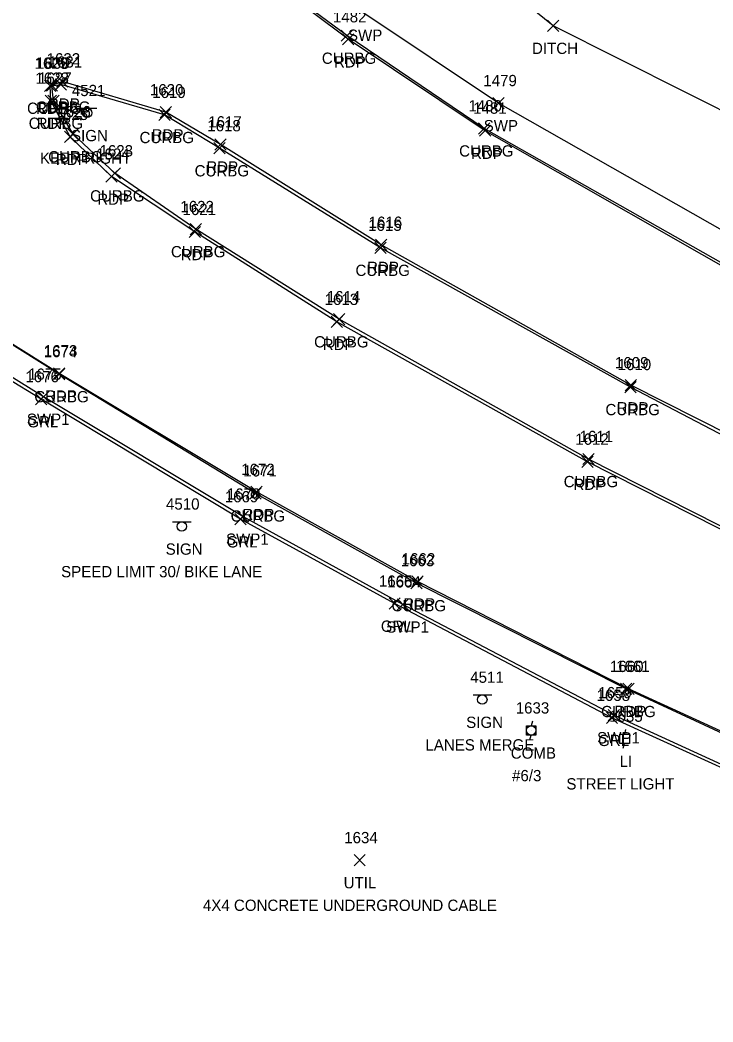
# Model space of a CAD drawing. Extents: x 1690689 to 1696275, y 438760 to 444007.
# Drawn here: x 1691973.1 to 1692096, y 439004.8 to 439182.5 of the extents above; entities that cross this region are included whole.
import ezdxf

# ---------------------------------------------------------------- set-up
doc = ezdxf.new("R2010")
doc.units = 0
for name, color, linetype in [('D_A', 7, 'Continuous'), ('D_TIC', 7, 'Continuous'), ('DD', 7, 'Continuous'), ('P_A', 7, 'Continuous'), ('P_I', 7, 'Continuous'), ('P_TIC', 7, 'Continuous'), ('PET', 7, 'Continuous'), ('R_A', 7, 'Continuous'), ('R_I', 7, 'Continuous'), ('R_TIC', 7, 'Continuous'), ('RC', 7, 'Continuous'), ('RGR', 7, 'Continuous'), ('RSW', 7, 'Continuous'), ('S_A', 7, 'Continuous'), ('S_C', 7, 'Continuous'), ('S_I', 7, 'Continuous'), ('SSGN', 7, 'Continuous'), ('U_A', 7, 'Continuous'), ('U_C', 7, 'Continuous'), ('U_I', 7, 'Continuous'), ('UDEFAULT', 7, 'Continuous'), ('ULP', 7, 'Continuous'), ('UP', 7, 'Continuous')]:
    doc.layers.add(name, color=color, linetype=linetype)

msp = doc.modelspace()

# ---------------------------------------------------------------- linework, layer by layer
at = {"layer": 'D_TIC'}
for points in [[(1692066.68, 439180.46), (1692068.68, 439182.46)], [(1692068.68, 439180.46), (1692066.68, 439182.46)]]:
    msp.add_lwpolyline(points, dxfattribs=at)
at = {"layer": 'DD'}
msp.add_lwpolyline([(1692601.69, 439017.79), (1692563.37, 439021.21), (1692508.43, 439031.44), (1692465.47, 439040.14), (1692415.19, 439051.66), (1692376.4, 439060.91), (1692339.07, 439071.12), (1692282.68, 439087.44), (1692232.86, 439105.49), (1692192.88, 439120.62), (1692157.57, 439136.03), (1692114.74, 439157.79), (1692067.68, 439181.46), (1692012.38, 439226.11), (1692016.4, 439238.61), (1692018.77, 439248.28), (1692013.27, 439253.9), (1692009.52, 439256.4)], dxfattribs=at)
at = {"layer": 'P_TIC'}
for points in [[(1692030.29, 439178.06), (1692032.29, 439180.06)], [(1692032.29, 439178.06), (1692030.29, 439180.06)], [(1691977.42, 439169.83), (1691979.42, 439171.83)], [(1691979.42, 439169.83), (1691977.42, 439171.83)], [(1691979.54, 439170.6), (1691981.54, 439172.6)], [(1691981.54, 439170.6), (1691979.54, 439172.6)], [(1691979.54, 439170.6), (1691981.54, 439172.6)], [(1691981.54, 439170.6), (1691979.54, 439172.6)], [(1691977.54, 439167.17), (1691979.54, 439169.17)], [(1691979.54, 439167.17), (1691977.54, 439169.17)], [(1691997.95, 439165.12), (1691999.95, 439167.12)], [(1691999.95, 439165.12), (1691997.95, 439167.12)], [(1691980.95, 439160.75), (1691982.95, 439162.75)], [(1691982.95, 439160.75), (1691980.95, 439162.75)], [(1692054.61, 439161.86), (1692056.61, 439163.86)], [(1692056.61, 439161.86), (1692054.61, 439163.86)], [(1692007.65, 439159.43), (1692009.65, 439161.43)], [(1692009.65, 439159.43), (1692007.65, 439161.43)], [(1691988.31, 439153.72), (1691990.31, 439155.72)], [(1691990.31, 439153.72), (1691988.31, 439155.72)], [(1692003.08, 439143.9), (1692005.08, 439145.9)], [(1692005.08, 439143.9), (1692003.08, 439145.9)], [(1692036.17, 439141.63), (1692038.17, 439143.63)], [(1692038.17, 439141.63), (1692036.17, 439143.63)], [(1692028.3, 439127.96), (1692030.3, 439129.96)], [(1692030.3, 439127.96), (1692028.3, 439129.96)], [(1691979.04, 439118.84), (1691981.04, 439120.84)], [(1691981.04, 439118.84), (1691979.04, 439120.84)], [(1692080.46, 439116.73), (1692082.46, 439118.73)], [(1692082.46, 439116.73), (1692080.46, 439118.73)], [(1692072.76, 439103.17), (1692074.76, 439105.17)], [(1692074.76, 439103.17), (1692072.76, 439105.17)], [(1692014.06, 439097.81), (1692016.06, 439099.81)], [(1692016.06, 439097.81), (1692014.06, 439099.81)], [(1692042.59, 439081.96), (1692044.59, 439083.96)], [(1692044.59, 439081.96), (1692042.59, 439083.96)], [(1692080.06, 439062.89), (1692082.06, 439064.89)], [(1692082.06, 439062.89), (1692080.06, 439064.89)]]:
    msp.add_lwpolyline(points, dxfattribs=at)
at = {"layer": 'PET'}
for points in [[(1692506.42, 439007.58), (1692409.86, 439027.99), (1692378.72, 439035.13), (1692333.82, 439046.83), (1692278.1, 439062.9), (1692234.78, 439077.7), (1692205.8, 439088.84), (1692153.42, 439111.21), (1692107.02, 439133.53), (1692055.61, 439162.86), (1692031.29, 439179.06), (1692011.62, 439193.84), (1692002.42, 439202.85), (1692001.04, 439204.48), (1691998.47, 439209.28), (1691996.33, 439214.88), (1691994.6, 439223.82), (1691994.86, 439229.58), (1691997.14, 439239.21), (1692003.46, 439250.16), (1692011.11, 439259.34), (1692010.11, 439260.69)], [(1692765.95, 438921.86), (1692671.87, 438941.97), (1692616.75, 438954.47), (1692587.11, 438960.22), (1692543.54, 438967.18), (1692506.54, 438970.09), (1692469.43, 438975.08), (1692419.94, 438983.98), (1692360.97, 438996.85), (1692305.33, 439011.12), (1692283.25, 439017.76), (1692237.36, 439032.88), (1692203.62, 439044.85), (1692162.64, 439062.19), (1692110.81, 439085.42), (1692073.76, 439104.17), (1692029.3, 439128.96), (1692004.08, 439144.9), (1691989.31, 439154.72), (1691981.95, 439161.75), (1691978.54, 439168.17), (1691978.42, 439170.83), (1691980.54, 439171.6)], [(1692767.64, 438925.55), (1692673.48, 438945.69), (1692617.32, 438957.74), (1692543.2, 438973.83), (1692470.55, 438989.57), (1692418.41, 439000.55), (1692365.96, 439012.47), (1692309.7, 439026.97), (1692288.49, 439033.25), (1692244.35, 439047.34), (1692210.04, 439059.59), (1692168.81, 439075.98), (1692116.96, 439099.81), (1692081.46, 439117.73), (1692037.17, 439142.63), (1692008.65, 439160.43), (1691998.95, 439166.12), (1691980.54, 439171.6)], [(1692485.07, 438945.57), (1692435.03, 438955.4), (1692385.23, 438965.25), (1692340.43, 438974.31), (1692296.87, 438984.77), (1692272.43, 438991.45), (1692235.97, 439002.41), (1692197.17, 439015.62), (1692153.62, 439031.87), (1692118.48, 439046.77), (1692081.06, 439063.89), (1692043.59, 439082.96), (1692015.06, 439098.81), (1691980.04, 439119.84), (1691962.57, 439130.66), (1691955.71, 439134.26), (1691947.97, 439136.72), (1691941.75, 439137.91), (1691935.77, 439138.24), (1691931.84, 439138.11), (1691929.14, 439137.6), (1691914.86, 439134.28)]]:
    msp.add_lwpolyline(points, dxfattribs=at)
at = {"layer": 'R_TIC'}
for points in [[(1692030.04, 439178.71), (1692032.04, 439180.71)], [(1692032.04, 439178.71), (1692030.04, 439180.71)], [(1691977.75, 439169.84), (1691979.75, 439171.84)], [(1691979.75, 439169.84), (1691977.75, 439171.84)], [(1691979.34, 439170.05), (1691981.34, 439172.05)], [(1691981.34, 439170.05), (1691979.34, 439172.05)], [(1691979.34, 439170.05), (1691981.34, 439172.05)], [(1691981.34, 439170.05), (1691979.34, 439172.05)], [(1691978.04, 439167.18), (1691980.04, 439169.18)], [(1691980.04, 439167.18), (1691978.04, 439169.18)], [(1692056.98, 439166.75), (1692058.98, 439168.75)], [(1692058.98, 439166.75), (1692056.98, 439168.75)], [(1691997.71, 439164.65), (1691999.71, 439166.65)], [(1691999.71, 439164.65), (1691997.71, 439166.65)], [(1691981.48, 439161.24), (1691983.48, 439163.24)], [(1691983.48, 439161.24), (1691981.48, 439163.24)], [(1692054.41, 439162.27), (1692056.41, 439164.27)], [(1692056.41, 439162.27), (1692054.41, 439164.27)], [(1692007.48, 439158.75), (1692009.48, 439160.75)], [(1692009.48, 439158.75), (1692007.48, 439160.75)], [(1691988.92, 439154.3), (1691990.92, 439156.3)], [(1691990.92, 439154.3), (1691988.92, 439156.3)], [(1692003.27, 439144.41), (1692005.27, 439146.41)], [(1692005.27, 439144.41), (1692003.27, 439146.41)], [(1692036.02, 439141.1), (1692038.02, 439143.1)], [(1692038.02, 439141.1), (1692036.02, 439143.1)], [(1692028.68, 439128.43), (1692030.68, 439130.43)], [(1692030.68, 439128.43), (1692028.68, 439130.43)], [(1691979.03, 439118.7), (1691981.03, 439120.7)], [(1691981.03, 439118.7), (1691979.03, 439120.7)], [(1692080.37, 439116.41), (1692082.37, 439118.41)], [(1692082.37, 439116.41), (1692080.37, 439118.41)], [(1691976.25, 439114.7), (1691978.25, 439116.7)], [(1691978.25, 439114.7), (1691976.25, 439116.7)], [(1691975.83, 439114.26), (1691977.83, 439116.26)], [(1691977.83, 439114.26), (1691975.83, 439116.26)], [(1692072.96, 439103.65), (1692074.96, 439105.65)], [(1692074.96, 439103.65), (1692072.96, 439105.65)], [(1692013.87, 439097.55), (1692015.87, 439099.55)], [(1692015.87, 439097.55), (1692013.87, 439099.55)], [(1692011.59, 439093.44), (1692013.59, 439095.44)], [(1692013.59, 439093.44), (1692011.59, 439095.44)], [(1692011.2, 439092.97), (1692013.2, 439094.97)], [(1692013.2, 439092.97), (1692011.2, 439094.97)], [(1692042.41, 439081.64), (1692044.41, 439083.64)], [(1692044.41, 439081.64), (1692042.41, 439083.64)], [(1692038.55, 439078.01), (1692040.55, 439080.01)], [(1692040.55, 439078.01), (1692038.55, 439080.01)], [(1692040.02, 439077.87), (1692042.02, 439079.87)], [(1692042.02, 439077.87), (1692040.02, 439079.87)], [(1692079.62, 439062.88), (1692081.62, 439064.88)], [(1692081.62, 439062.88), (1692079.62, 439064.88)], [(1692077.11, 439057.76), (1692079.11, 439059.76)], [(1692079.11, 439057.76), (1692077.11, 439059.76)], [(1692077.43, 439058.23), (1692079.43, 439060.23)], [(1692079.43, 439058.23), (1692077.43, 439060.23)]]:
    msp.add_lwpolyline(points, dxfattribs=at)
at = {"layer": 'RC'}
for points in [[(1692458.66, 439018.07), (1692409.83, 439028.32), (1692378.84, 439035.52), (1692333.85, 439047.39), (1692278.2, 439063.36), (1692234.93, 439078.32), (1692206.05, 439089.01), (1692153.68, 439111.65), (1692107.21, 439133.95), (1692055.41, 439163.27), (1692031.04, 439179.71), (1692011.71, 439194.03), (1692002.37, 439202.91), (1692001.39, 439204.32), (1691998.83, 439209.21), (1691996.61, 439215.03), (1691994.98, 439223.75), (1691995.26, 439229.27), (1691997.49, 439239.08), (1692003.79, 439249.87), (1692007.64, 439254.1)], [(1692766.36, 438922.45), (1692671.96, 438942.46), (1692616.73, 438954.89), (1692587.1, 438960.64), (1692543.8, 438967.52), (1692506.49, 438970.64), (1692469.42, 438975.23), (1692419.64, 438984.49), (1692361.22, 438997.2), (1692305.35, 439011.89), (1692283.35, 439018.43), (1692237.58, 439033.34), (1692203.77, 439045.28), (1692162.83, 439062.74), (1692110.99, 439085.87), (1692073.96, 439104.65), (1692029.68, 439129.43), (1692004.27, 439145.41), (1691989.92, 439155.3), (1691982.48, 439162.24), (1691979.04, 439168.18), (1691978.75, 439170.84), (1691980.34, 439171.05)], [(1692767.42, 438924.95), (1692673.21, 438945.2), (1692617.12, 438957.34), (1692543.19, 438973.28), (1692470.51, 438988.93), (1692418.35, 439000.23), (1692365.64, 439012.16), (1692309.62, 439026.54), (1692288.66, 439032.69), (1692244.17, 439046.9), (1692209.98, 439058.96), (1692168.78, 439075.61), (1692116.61, 439099.03), (1692081.37, 439117.41), (1692037.02, 439142.1), (1692008.48, 439159.75), (1691998.71, 439165.65), (1691980.34, 439171.05)], [(1692118.26, 439046.46), (1692080.62, 439063.88), (1692043.41, 439082.64), (1692014.87, 439098.55), (1691980.03, 439119.7), (1691962.53, 439130.63), (1691955.49, 439134.15), (1691948, 439136.19), (1691941.67, 439137.59), (1691935.68, 439137.8), (1691931.95, 439137.88), (1691929.4, 439137.32), (1691914.96, 439133.89), (1691889.69, 439124), (1691873.84, 439117.58), (1691827.75, 439101.2)]]:
    msp.add_lwpolyline(points, dxfattribs=at)
at = {"layer": 'RGR'}
msp.add_lwpolyline([(1692115.78, 439041.61), (1692078.11, 439058.76), (1692039.55, 439079.01), (1692012.2, 439093.97), (1691976.83, 439115.26), (1691958.12, 439126.58), (1691952.53, 439129.47), (1691946.71, 439131.26), (1691941.09, 439132.25), (1691934.38, 439132.69), (1691928.78, 439132.18), (1691917.8, 439129.38), (1691893.03, 439121.47), (1691884.65, 439119.11), (1691880.06, 439116.74), (1691874.97, 439112.92)], dxfattribs=at)
at = {"layer": 'RSW'}
for points in [[(1692665.59, 438979.47), (1692633.47, 438986.11), (1692606.01, 438992.31), (1692555.68, 439002.49), (1692507.66, 439012.62), (1692459.75, 439022.83), (1692410.78, 439033.39), (1692380.42, 439040.26), (1692334.91, 439052.16), (1692279.52, 439068.27), (1692236.35, 439083.17), (1692207.73, 439093.85), (1692155.83, 439116.19), (1692109.79, 439138.3), (1692057.98, 439167.75), (1692033.9, 439183.79), (1692014.53, 439197.98), (1692008.04, 439204.8), (1692006.24, 439207.82), (1692001.39, 439204.32)], [(1692637.9, 438909.12), (1692604.66, 438916.25), (1692559.9, 438925.87), (1692526.71, 438932.34), (1692484.3, 438940.72), (1692434.26, 438950.4), (1692384.3, 438960.21), (1692339.45, 438969.35), (1692295.64, 438980.27), (1692271.48, 438986.87), (1692234.38, 438997.66), (1692195.38, 439010.77), (1692151.68, 439027.12), (1692116.08, 439041.96), (1692078.43, 439059.23), (1692041.02, 439078.87), (1692012.59, 439094.44), (1691977.25, 439115.7), (1691958.72, 439127.11), (1691952.86, 439130.25), (1691946.68, 439131.94), (1691948, 439136.19)]]:
    msp.add_lwpolyline(points, dxfattribs=at)
at = {"layer": 'SSGN'}
for p, q in [((1691983.35, 439166.84), (1691986.68, 439166.84)), ((1691984.99, 439166.01), (1691984.99, 439166.01)), ((1692000.13, 439093.54), (1692003.47, 439093.54)), ((1692001.78, 439092.7), (1692001.78, 439092.7)), ((1692053.46, 439062.83), (1692056.79, 439062.83)), ((1692055.1, 439061.99), (1692055.1, 439061.99))]:
    msp.add_line(p, q, dxfattribs=at)
for centre in [(1691984.99, 439166.01), (1692001.78, 439092.7), (1692055.1, 439061.99)]:
    msp.add_circle(centre, 0.833, dxfattribs=at)
at = {"layer": 'UDEFAULT'}
for points in [[(1692032.34, 439032.53), (1692034.34, 439034.53)], [(1692034.34, 439032.53), (1692032.34, 439034.53)]]:
    msp.add_lwpolyline(points, dxfattribs=at)
at = {"layer": 'ULP'}
for p, q in [((1692080.52, 439056.72), (1692080.35, 439055.89)), ((1692079.52, 439054.22), (1692079.52, 439055.89)), ((1692079.52, 439055.89), (1692081.19, 439055.89)), ((1692080.35, 439055.06), (1692080.35, 439055.06)), ((1692081.19, 439055.89), (1692081.19, 439054.22)), ((1692081.19, 439054.22), (1692079.52, 439054.22)), ((1692080.1, 439053.39), (1692080.35, 439054.22))]:
    msp.add_line(p, q, dxfattribs=at)
at = {"layer": 'UP'}
for p, q in [((1692064.02, 439058.19), (1692063.77, 439057.36)), ((1692062.93, 439055.69), (1692062.93, 439057.36)), ((1692062.93, 439057.36), (1692064.6, 439057.36)), ((1692063.77, 439056.52), (1692063.77, 439056.52)), ((1692064.6, 439057.36), (1692064.6, 439055.69)), ((1692064.6, 439055.69), (1692062.93, 439055.69)), ((1692063.52, 439054.86), (1692063.77, 439055.69))]:
    msp.add_line(p, q, dxfattribs=at)
msp.add_circle((1692063.77, 439056.52), 0.833, dxfattribs=at)

# ---------------------------------------------------------------- texts
at = {"layer": 'D_A'}
msp.add_text('DITCH', height=2, dxfattribs=at).set_placement((1692063.92, 439176.46))
at = {"layer": 'P_A'}
for p in [(1692028.78, 439174.06), (1691978.03, 439166.6), (1691978.03, 439166.6), (1691975.91, 439165.83), (1691976.03, 439163.17), (1691996.44, 439161.12), (1692053.1, 439157.86), (1691979.44, 439156.75), (1692006.13, 439155.43), (1691986.79, 439149.72), (1692001.57, 439139.9), (1692034.66, 439137.63), (1692026.79, 439123.96), (1691977.52, 439114.84), (1692078.94, 439112.73), (1692071.25, 439099.17), (1692012.55, 439093.81), (1692041.08, 439077.96), (1692078.55, 439058.89)]:
    msp.add_text('RDP', height=2, dxfattribs=at).set_placement(p)
at = {"layer": 'P_I'}
for s, p in [('1482', (1692028.6, 439182.06)), ('1629', (1691975.67, 439173.83)), ('1632', (1691977.8, 439174.6)), ('1632', (1691977.8, 439174.6)), ('1628', (1691975.8, 439171.17)), ('1620', (1691996.12, 439169.12)), ('1625', (1691979.21, 439164.75)), ('1481', (1692053.48, 439165.86)), ('1617', (1692006.47, 439163.43)), ('1624', (1691986.57, 439157.72)), ('1621', (1692001.91, 439147.9)), ('1616', (1692034.94, 439145.63)), ('1613', (1692027.12, 439131.96)), ('1673', (1691977.3, 439122.84)), ('1609', (1692078.63, 439120.73)), ('1612', (1692071.59, 439107.17)), ('1672', (1692012.32, 439101.81)), ('1662', (1692040.8, 439085.96)), ('1661', (1692078.84, 439066.89))]:
    msp.add_text(s, height=2, dxfattribs=at).set_placement(p)
at = {"layer": 'R_A'}
for s, p in [('SWP', (1692031.27, 439178.79)), ('CURBG', (1692026.63, 439174.71)), ('CURBG', (1691975.92, 439166.05)), ('CURBG', (1691975.92, 439166.05)), ('CURBG', (1691974.33, 439165.84)), ('CURBG', (1691974.62, 439163.18)), ('SWP', (1692055.35, 439162.75)), ('CURBG', (1691994.29, 439160.65)), ('CURBG', (1691978.07, 439157.24)), ('CURBG', (1692050.99, 439158.27)), ('CURBG', (1692004.06, 439154.75)), ('CURBG', (1691985.51, 439150.3)), ('CURBG', (1691999.86, 439140.41)), ('CURBG', (1692032.6, 439137.1)), ('CURBG', (1692025.26, 439124.43)), ('CURBG', (1691975.61, 439114.7)), ('CURBG', (1692076.95, 439112.41)), ('SWP1', (1691974.29, 439110.7)), ('GRL', (1691974.37, 439110.26)), ('CURBG', (1692069.54, 439099.65)), ('CURBG', (1692010.45, 439093.55)), ('SWP1', (1692009.63, 439089.44)), ('GRL', (1692009.74, 439088.97)), ('CURBG', (1692039, 439077.64)), ('GRL', (1692037.1, 439074.01)), ('SWP1', (1692038.06, 439073.87)), ('CURBG', (1692076.2, 439058.88)), ('SWP1', (1692075.47, 439054.23)), ('GRL', (1692075.65, 439053.76))]:
    msp.add_text(s, height=2, dxfattribs=at).set_placement(p)
at = {"layer": 'R_I'}
for s, p in [('1630', (1691975.92, 439173.84)), ('1631', (1691978.16, 439174.05)), ('1631', (1691978.16, 439174.05)), ('1627', (1691976.29, 439171.18)), ('1479', (1692055.28, 439170.75)), ('1619', (1691996.53, 439168.65)), ('1480', (1692052.63, 439166.27)), ('1626', (1691979.69, 439165.24)), ('1618', (1692006.3, 439162.75)), ('1623', (1691987.18, 439158.3)), ('1622', (1692001.53, 439148.41)), ('1615', (1692034.84, 439145.1)), ('1614', (1692027.5, 439132.43)), ('1674', (1691977.28, 439122.7)), ('1610', (1692079.11, 439120.41)), ('1676', (1691974.03, 439118.26)), ('1675', (1691974.51, 439118.7)), ('1611', (1692072.35, 439107.65)), ('1671', (1692012.7, 439101.55)), ('1669', (1692009.41, 439096.97)), ('1670', (1692009.77, 439097.44)), ('1663', (1692040.63, 439085.64)), ('1665', (1692036.76, 439082.01)), ('1664', (1692038.23, 439081.87)), ('1660', (1692077.75, 439066.88)), ('1658', (1692075.37, 439061.76)), ('1659', (1692075.68, 439062.23))]:
    msp.add_text(s, height=2, dxfattribs=at).set_placement(p)
at = {"layer": 'S_A'}
for p in [(1691982.13, 439160.99), (1691998.92, 439087.68), (1692052.24, 439056.97)]:
    msp.add_text('SIGN', height=2, dxfattribs=at).set_placement(p)
at = {"layer": 'S_C'}
for s, p in [('KEEP RIGHT', (1691976.62, 439156.99)), ('SPEED LIMIT 30/ BIKE LANE', (1691980.37, 439083.68)), ('LANES MERGE', (1692045.01, 439052.97))]:
    msp.add_text(s, height=2, dxfattribs=at).set_placement(p)
at = {"layer": 'S_I'}
for s, p in [('4521', (1691982.28, 439168.99)), ('4510', (1691998.98, 439095.68)), ('4511', (1692052.96, 439064.97))]:
    msp.add_text(s, height=2, dxfattribs=at).set_placement(p)
at = {"layer": 'U_A'}
for s, p in [('COMB', (1692060.15, 439051.52)), ('LI', (1692079.46, 439050.06)), ('UTIL', (1692030.5, 439028.53))]:
    msp.add_text(s, height=2, dxfattribs=at).set_placement(p)
at = {"layer": 'U_C'}
for s, p in [('#6/3', (1692060.38, 439047.52)), ('STREET LIGHT', (1692070.02, 439046.06)), ('4X4 CONCRETE UNDERGROUND CABLE', (1692005.53, 439024.53))]:
    msp.add_text(s, height=2, dxfattribs=at).set_placement(p)
at = {"layer": 'U_I'}
for s, p in [('1633', (1692061.03, 439059.52)), ('1635', (1692077.61, 439058.06)), ('1634', (1692030.6, 439036.53))]:
    msp.add_text(s, height=2, dxfattribs=at).set_placement(p)

doc.saveas('drawing.dxf')
